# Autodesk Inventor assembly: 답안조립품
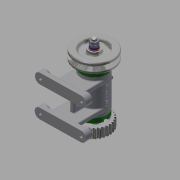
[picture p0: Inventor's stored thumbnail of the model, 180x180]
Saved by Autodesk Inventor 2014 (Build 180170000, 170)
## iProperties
Created: 2015-11
Part Number: 답안조립품
Document SubType Name: Assembly
Designer: L10
Author: L10
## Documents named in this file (15)
- C:\Users\L10\Desktop\451110V1024\답안조립품.iam
- C:\Users\L10\Desktop\451110V1024\본체.ipt
- C:\Users\L10\Desktop\451110V1024\커버.ipt
- C:\Users\L10\Desktop\451110V1024\오일 실 15 25 7.ipt
- C:\Users\L10\Desktop\451110V1024\베어링 15 x 32 x 9.ipt
- C:\Users\L10\Desktop\451110V1024\축.ipt
- C:\Users\L10\Desktop\451110V1024\키 3 x 3 x 12.ipt
- C:\Users\L10\Desktop\451110V1024\V벨트풀리.ipt
- C:\Users\L10\Desktop\451110V1024\스퍼기어.ipt
- C:\Users\L10\Desktop\451110V1024\와셔 8x17.ipt
- C:\Users\L10\Desktop\451110V1024\스프링와셔 8.ipt
- C:\Users\L10\Desktop\451110V1024\너트 M 8.ipt
- C:\Users\L10\Desktop\451110V1024\니플 M 6 x 0.75.ipt
- C:\Users\L10\Desktop\451110V1024\와셔 6x11.5.ipt
- C:\Users\L10\Desktop\451110V1024\볼트 M 6 x 8.ipt
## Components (3 placed, 2 different names)
1. KS B 2023 6002 - 15 x 32 x 9:1
2. KS B 2023 6002 - 15 x 32 x 9:2
3. V벨트풀리:1
